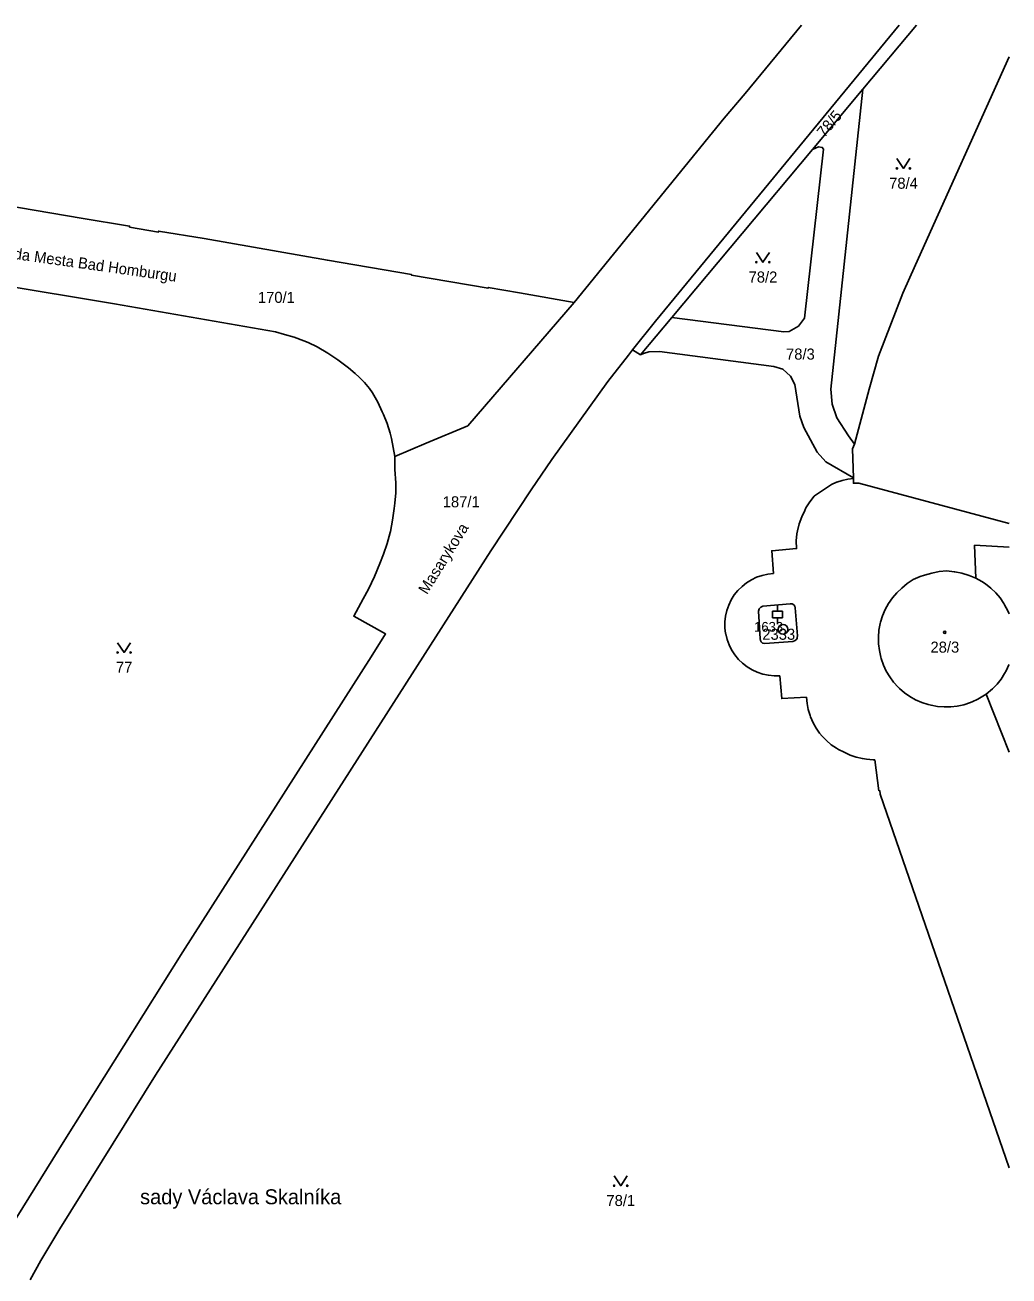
# Model space of a CAD drawing. Extents: x -866441 to -866144, y -1037389 to -1036968.
# Drawn here: x -866295.1 to -866143.8, y -1037160.7 to -1036968.4 of the extents above; entities that cross this region are included whole.
import ezdxf

# ---------------------------------------------------------------- set-up
doc = ezdxf.new("R2010")
doc.units = 0
for name, color, linetype in [('Hranice parcel', 7, 'Continuous'), ('Parcelní čísla', 7, 'Continuous'), ('Pop  PČ popisy', 7, 'Continuous'), ('Značky bodu BP', 7, 'Continuous'), ('Značky budov', 7, 'Continuous'), ('Značky kultur', 7, 'Continuous')]:
    doc.layers.add(name, color=color, linetype=linetype)

msp = doc.modelspace()

# ---------------------------------------------------------------- linework, layer by layer
at = {"layer": 'Hranice parcel'}
for p, q in [((-866158.02, -1036968.36), (-866166.25, -1036978.2)), ((-866166.25, -1036978.2), (-866174.02, -1036987.48)), ((-866174.02, -1036987.48), (-866195.66, -1037013.35)), ((-866195.66, -1037013.35), (-866200.46, -1037019.09)), ((-866201.68, -1037018.3), (-866202.32, -1037019.11)), ((-866200.46, -1037019.09), (-866201.68, -1037018.3)), ((-866238.24, -1037034.71), (-866238.76, -1037031.92)), ((-866238.24, -1037034.71), (-866233.46, -1037032.64)), ((-866167.72, -1037038.12), (-866167.72, -1037037.97)), ((-866149.08, -1037048.34), (-866148.88, -1037053.44)), ((-866176.65, -1037057.98), (-866176.33, -1037062.29)), ((-866177.03, -1037063.16), (-866181.32, -1037063.48)), ((-866147.31, -1037071.24), (-866148.56, -1037072.03)), ((-866146.32, -1037070.42), (-866147.31, -1037071.24)), ((-866164.4, -1037081.34), (-866164.69, -1037081.35))]:
    msp.add_line(p, q, dxfattribs=at)
for points in [[(-866210.68, -1037011.04), (-866187.6, -1036982.68), (-866184.36, -1036978.88), (-866175.7, -1036968.36)], [(-866160.67, -1036968.36), (-866198.18, -1037013.9), (-866201.68, -1037018.3)], [(-866167.57, -1037032.81), (-866165.29, -1037024.36), (-866163.86, -1037019.3), (-866160.09, -1037009.57), (-866158.16, -1037005.22), (-866143.78, -1036973.23)], [(-866167.57, -1037032.81), (-866168.45, -1037031.55), (-866170.24, -1037028.78), (-866171, -1037026.69), (-866171.18, -1037024.34), (-866166.25, -1036978.2)], [(-866195.66, -1037013.35), (-866178.44, -1037015.55), (-866177.62, -1037015.49), (-866176.18, -1037014.68), (-866175.22, -1037013.46), (-866172.34, -1036987.45), (-866172.5, -1036987.17), (-866173.08, -1036987.11), (-866174.02, -1036987.48)], [(-866305.22, -1036994.87), (-866286.5, -1036998.04), (-866279.05, -1036999.29), (-866279.07, -1036999.44), (-866274.61, -1037000.19), (-866274.59, -1037000.04), (-866267.61, -1037001.21), (-866248.62, -1037004.54), (-866235.67, -1037006.74), (-866235.69, -1037006.83), (-866223.91, -1037008.83), (-866223.89, -1037008.71), (-866219.08, -1037009.53), (-866210.68, -1037011.04)], [(-866255.23, -1037015.93), (-866256.61, -1037015.56), (-866281.38, -1037011.26), (-866336.35, -1037002.11), (-866338.61, -1037001.97)], [(-866233.46, -1037032.64), (-866227.05, -1037029.99), (-866210.68, -1037011.04)], [(-866238.76, -1037031.92), (-866238.98, -1037031.1), (-866239.45, -1037029.66), (-866240.01, -1037028.25), (-866240.19, -1037027.83), (-866240.89, -1037026.36), (-866241.67, -1037024.94), (-866242.17, -1037024.25), (-866242.92, -1037023.35), (-866243.74, -1037022.52), (-866244.36, -1037021.93), (-866245.36, -1037021.08), (-866246.43, -1037020.31), (-866247.02, -1037019.87), (-866248.58, -1037018.81), (-866250.19, -1037017.84), (-866251.6, -1037017.17), (-866252.26, -1037016.9), (-866253.73, -1037016.37), (-866255.23, -1037015.93)], [(-866202.32, -1037019.11), (-866205.51, -1037023.16), (-866214.08, -1037035.18), (-866217.27, -1037039.83), (-866223.47, -1037049.2), (-866275.07, -1037129.84), (-866289.8, -1037153.5), (-866292.71, -1037158.35), (-866294.34, -1037161.34)], [(-866167.72, -1037037.97), (-866171.97, -1037035.51), (-866173.28, -1037034.04), (-866175.36, -1037030.27), (-866175.95, -1037028.49), (-866176.75, -1037023.64), (-866177.38, -1037022.37), (-866178.55, -1037021.29), (-866179.97, -1037020.85), (-866197.54, -1037018.54), (-866199.19, -1037018.6), (-866200.01, -1037018.87), (-866200.46, -1037019.09)], [(-866167.72, -1037037.97), (-866167.83, -1037033.55), (-866167.57, -1037032.81)], [(-866238.08, -1037038.74), (-866238.23, -1037036.73), (-866238.24, -1037034.71)], [(-866243.12, -1037056.62), (-866242.31, -1037055.09), (-866241.39, -1037053.16), (-866240.56, -1037051.18), (-866239.99, -1037049.74), (-866239.44, -1037048.09), (-866238.98, -1037046.41), (-866238.94, -1037046.25), (-866238.6, -1037044.5), (-866238.36, -1037042.73), (-866238.25, -1037041.9), (-866238.11, -1037040.32), (-866238.08, -1037038.74)], [(-866176.53, -1037047.69), (-866176.4, -1037046.59), (-866176.31, -1037046.12), (-866176.04, -1037045.05), (-866175.67, -1037044.01), (-866175.21, -1037043), (-866175.01, -1037042.63), (-866174.43, -1037041.69), (-866173.77, -1037040.8), (-866173.69, -1037040.74), (-866171.07, -1037039.04), (-866170.29, -1037038.67), (-866170.26, -1037038.66), (-866169.43, -1037038.38), (-866168.58, -1037038.2), (-866167.72, -1037038.12)], [(-866167.72, -1037038.12), (-866167.72, -1037038.82), (-866166.87, -1037038.82), (-866143.78, -1037045)], [(-866180.02, -1037052.71), (-866180.28, -1037049.2), (-866176.46, -1037048.87), (-866176.53, -1037047.69)], [(-866143.78, -1037048.67), (-866149.08, -1037048.34)], [(-866179.02, -1037068.42), (-866179.91, -1037068.44), (-866180.79, -1037068.35), (-866181.66, -1037068.17), (-866182.5, -1037067.9), (-866183.31, -1037067.52), (-866184.07, -1037067.07), (-866184.77, -1037066.52), (-866185.41, -1037065.91), (-866185.97, -1037065.22), (-866186.45, -1037064.47), (-866186.85, -1037063.68), (-866187.15, -1037062.85), (-866187.36, -1037061.99), (-866187.37, -1037061.92), (-866187.47, -1037061.04), (-866187.48, -1037060.15), (-866187.38, -1037059.27), (-866187.18, -1037058.4), (-866186.89, -1037057.57), (-866186.51, -1037056.77), (-866186.04, -1037056.01), (-866185.48, -1037055.32), (-866184.85, -1037054.69), (-866184.16, -1037054.14), (-866183.41, -1037053.67), (-866182.61, -1037053.29), (-866181.77, -1037053), (-866180.9, -1037052.81), (-866180.02, -1037052.71)], [(-866148.56, -1037072.03), (-866149.47, -1037072.46), (-866150.42, -1037072.8), (-866150.74, -1037072.89), (-866151.73, -1037073.1), (-866152.73, -1037073.22), (-866153.74, -1037073.23), (-866154.76, -1037073.16), (-866155.76, -1037072.98), (-866156.24, -1037072.86), (-866157.21, -1037072.54), (-866158.14, -1037072.13), (-866159.03, -1037071.63), (-866159.86, -1037071.04), (-866160.63, -1037070.38), (-866160.84, -1037070.17), (-866161.53, -1037069.42), (-866162.13, -1037068.6), (-866162.65, -1037067.72), (-866163.09, -1037066.78), (-866163.43, -1037065.79), (-866163.49, -1037065.58), (-866163.72, -1037064.56), (-866163.85, -1037063.53), (-866163.88, -1037062.49), (-866163.78, -1037061.44), (-866163.58, -1037060.41), (-866163.53, -1037060.2), (-866163.22, -1037059.2), (-866162.81, -1037058.23), (-866162.31, -1037057.31), (-866161.68, -1037056.43), (-866161.05, -1037055.7), (-866160.27, -1037054.94), (-866159.43, -1037054.25), (-866158.53, -1037053.65), (-866157.46, -1037053.19), (-866156.79, -1037052.95), (-866155.67, -1037052.64), (-866154.52, -1037052.42), (-866153.35, -1037052.3), (-866152.23, -1037052.43), (-866152.11, -1037052.45), (-866151.01, -1037052.68), (-866149.93, -1037053.01), (-866148.88, -1037053.44)], [(-866148.88, -1037053.44), (-866147.96, -1037053.95), (-866147.42, -1037054.31), (-866146.59, -1037054.96), (-866145.83, -1037055.68)], [(-866300.13, -1037157.61), (-866297.32, -1037153.2), (-866289.02, -1037139.82), (-866270.86, -1037110.87), (-866241.88, -1037065.54), (-866239.67, -1037062), (-866244.58, -1037059.28), (-866243.12, -1037056.62)], [(-866145.83, -1037055.68), (-866145.16, -1037056.47), (-866144.57, -1037057.33), (-866144.46, -1037057.51), (-866143.98, -1037058.43), (-866143.78, -1037058.9)], [(-866182.06, -1037062.73), (-866182.3, -1037058.49), (-866182.21, -1037058.16), (-866181.97, -1037057.88), (-866181.66, -1037057.73), (-866177.45, -1037057.35)], [(-866177.45, -1037057.35), (-866177.18, -1037057.37), (-866177.13, -1037057.38), (-866176.9, -1037057.52), (-866176.73, -1037057.72), (-866176.65, -1037057.98)], [(-866176.33, -1037062.29), (-866176.35, -1037062.57), (-866176.39, -1037062.68), (-866176.54, -1037062.92), (-866176.76, -1037063.08), (-866177.03, -1037063.16)], [(-866181.32, -1037063.48), (-866181.58, -1037063.44), (-866181.69, -1037063.4), (-866181.9, -1037063.23), (-866182.03, -1037062.99), (-866182.06, -1037062.73)], [(-866143.78, -1037066.73), (-866143.79, -1037066.75), (-866144.2, -1037067.66), (-866144.45, -1037068.11), (-866144.99, -1037068.94), (-866145.62, -1037069.71), (-866146.32, -1037070.42)], [(-866174.94, -1037071.71), (-866178.75, -1037071.93), (-866179.02, -1037068.42)], [(-866164.69, -1037081.35), (-866165.68, -1037081.28), (-866166.34, -1037081.18), (-866167.3, -1037080.95), (-866168.23, -1037080.62), (-866169.13, -1037080.2), (-866170, -1037079.77), (-866170.32, -1037079.58), (-866171.12, -1037079.03), (-866171.85, -1037078.4), (-866172.52, -1037077.73), (-866172.91, -1037077.26), (-866173.45, -1037076.48), (-866173.9, -1037075.65), (-866174.3, -1037074.77), (-866174.38, -1037074.56), (-866174.66, -1037073.63), (-866174.85, -1037072.68), (-866174.94, -1037071.71)], [(-866147.31, -1037071.24), (-866143.78, -1037080.17)], [(-866143.78, -1037144.11), (-866163.58, -1037086.66), (-866163.65, -1037086.09), (-866163.78, -1037086.11), (-866164.4, -1037081.34)]]:
    msp.add_lwpolyline(points, dxfattribs=at)
at = {"layer": 'Značky bodu BP'}
for radius in [0.75, 0.03]:
    msp.add_circle((-866178.54, -1037061.28), radius, dxfattribs=at)
at = {"layer": 'Značky budov'}
msp.add_circle((-866153.67, -1037061.75), 0.175, dxfattribs=at)
at = {"layer": 'Značky kultur'}
for p, q in [((-866180.14, -1037058.5), (-866178.64, -1037058.5)), ((-866180.14, -1037059.5), (-866180.14, -1037058.5)), ((-866179.39, -1037058.5), (-866179.39, -1037057.5)), ((-866178.64, -1037059.5), (-866178.64, -1037058.5)), ((-866180.14, -1037059.5), (-866178.64, -1037059.5)), ((-866179.39, -1037060.5), (-866179.39, -1037059.5))]:
    msp.add_line(p, q, dxfattribs=at)
for points in [[(-866161.02, -1036988.91), (-866160.02, -1036990.41), (-866159.02, -1036988.91)], [(-866182.64, -1037003.33), (-866181.64, -1037004.83), (-866180.64, -1037003.33)], [(-866280.9, -1037063.35), (-866279.9, -1037064.85), (-866278.9, -1037063.35)], [(-866204.51, -1037145.36), (-866203.51, -1037146.86), (-866202.51, -1037145.36)]]:
    msp.add_lwpolyline(points, dxfattribs=at)
for centre in [(-866161.02, -1036990.41), (-866159.02, -1036990.41), (-866182.64, -1037004.83), (-866180.64, -1037004.83), (-866280.9, -1037064.85), (-866278.9, -1037064.85), (-866204.51, -1037146.86), (-866202.51, -1037146.86)]:
    msp.add_circle(centre, 0.1, dxfattribs=at)

# ---------------------------------------------------------------- texts
at = {"layer": 'Parcelní čísla'}
msp.add_text('78/5', height=1.7, rotation=50, dxfattribs=at).set_placement((-866172.19, -1036985.77))
for s, p in [('78/4', (-866162.22, -1036993.54)), ('78/2', (-866183.84, -1037007.96)), ('170/1', (-866259.32, -1037011.09)), ('78/3', (-866178.08, -1037019.81)), ('187/1', (-866230.89, -1037042.53)), ('2333', (-866181.73, -1037062.9)), ('28/3', (-866155.86, -1037064.88)), ('77', (-866281.16, -1037067.97)), ('78/1', (-866205.71, -1037149.98))]:
    msp.add_text(s, height=1.7, dxfattribs=at).set_placement(p)
at = {"layer": 'Pop  PČ popisy'}
for s, rotation, p in [('Promenáda Mesta Bad Homburgu', 352, (-866306.1, -1037003.04)), ('Masarykova', 58, (-866233.32, -1037056.04))]:
    msp.add_text(s, height=1.7, rotation=rotation, dxfattribs=at).set_placement(p)
msp.add_text('sady Václava Skalníka', height=2.3, dxfattribs=at).set_placement((-866277.44, -1037149.71))
at = {"layer": 'Značky bodu BP'}
msp.add_text('1633', height=1.5, dxfattribs=at).set_placement((-866182.99, -1037061.66))

doc.saveas('drawing.dxf')
